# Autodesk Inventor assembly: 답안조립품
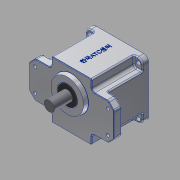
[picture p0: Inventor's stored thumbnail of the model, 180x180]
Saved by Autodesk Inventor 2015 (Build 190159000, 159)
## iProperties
Created: 2016-02
Part Number: 답안조립품
Document SubType Name: Assembly
Designer: Administrator
Author: Administrator
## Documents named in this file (10)
- C:\Users\Administrator\Desktop\460209V1015\답안조립품.iam
- C:\Users\Administrator\Desktop\460209V1015\본체.ipt
- C:\Users\Administrator\Desktop\460209V1015\커버.ipt
- C:\Users\Administrator\Desktop\460209V1015\볼트 M4 x 10.ipt
- C:\Users\Administrator\Desktop\460209V1015\오일실 8 22 7.ipt
- C:\Users\Administrator\Desktop\460209V1015\오일실 17 32 8.ipt
- C:\Users\Administrator\Desktop\460209V1015\베어링 608.ipt
- C:\Users\Administrator\Desktop\460209V1015\베어링 6003.ipt
- C:\Users\Administrator\Desktop\460209V1015\메인축.ipt
- C:\Users\Administrator\Desktop\460209V1015\서브축.ipt
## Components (2 placed, 1 different names)
1. ISO 4762 M4 x 10:1 — Insert:1
2. ISO 4762 M4 x 10:2 — Insert:2
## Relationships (2: Insert 2)
- Insert:1: ISO 4762 M4 x 10:1
- Insert:2: ISO 4762 M4 x 10:2
